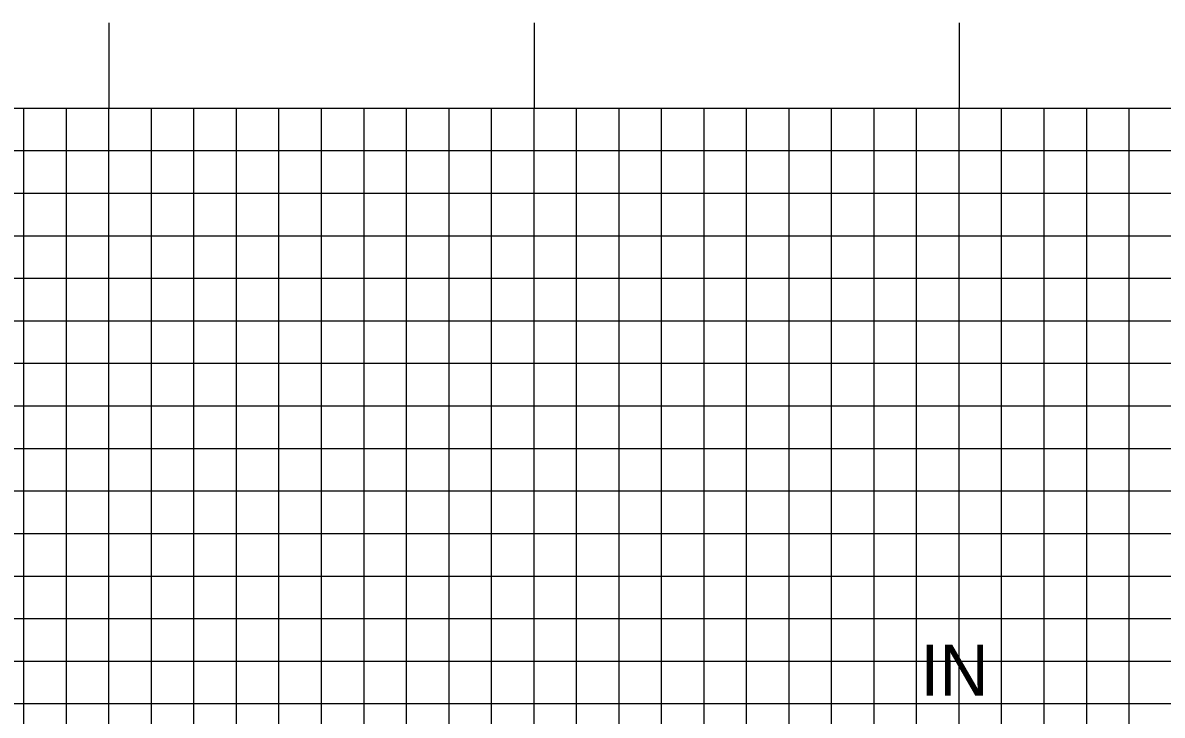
# Model space of a CAD drawing. Extents: x 851348 to 851692, y 364785 to 365005.
# Drawn here: x 851532.16 to 851558.97, y 364823.96 to 364840.24 of the extents above; entities that cross this region are included whole.
import ezdxf

# ---------------------------------------------------------------- set-up
doc = ezdxf.new("R2010")
doc.units = 0
for name, color, linetype in [('ANNOTATION', 7, 'Continuous'), ('MAJOR', 7, 'Continuous'), ('MINOR', 7, 'Continuous')]:
    doc.layers.add(name, color=color, linetype=linetype)

msp = doc.modelspace()

# ---------------------------------------------------------------- linework, layer by layer
at = {"layer": 'MAJOR'}
for p, q in [((851534.191, 364840.237), (851534.191, 364838.233)), ((851544.191, 364840.237), (851544.191, 364838.233)), ((851554.191, 364840.237), (851554.191, 364838.233)), ((851374.191, 364838.233), (851654.191, 364838.233)), ((851374.191, 364838.233), (851654.191, 364838.233)), ((851534.191, 364808.233), (851534.191, 364838.233)), ((851544.191, 364808.233), (851544.191, 364838.233)), ((851554.191, 364808.233), (851554.191, 364838.233)), ((851374.191, 364833.233), (851654.191, 364833.233)), ((851374.191, 364828.233), (851654.191, 364828.233))]:
    msp.add_line(p, q, dxfattribs=at)
at = {"layer": 'MINOR'}
for p, q in [((851532.191, 364808.233), (851532.191, 364838.233)), ((851533.191, 364808.233), (851533.191, 364838.233)), ((851535.191, 364808.233), (851535.191, 364838.233)), ((851536.191, 364808.233), (851536.191, 364838.233)), ((851537.191, 364808.233), (851537.191, 364838.233)), ((851538.191, 364808.233), (851538.191, 364838.233)), ((851539.191, 364808.233), (851539.191, 364838.233)), ((851540.191, 364808.233), (851540.191, 364838.233)), ((851541.191, 364808.233), (851541.191, 364838.233)), ((851542.191, 364808.233), (851542.191, 364838.233)), ((851543.191, 364808.233), (851543.191, 364838.233)), ((851545.191, 364808.233), (851545.191, 364838.233)), ((851546.191, 364808.233), (851546.191, 364838.233)), ((851547.191, 364808.233), (851547.191, 364838.233)), ((851548.191, 364808.233), (851548.191, 364838.233)), ((851549.191, 364808.233), (851549.191, 364838.233)), ((851550.191, 364808.233), (851550.191, 364838.233)), ((851551.191, 364808.233), (851551.191, 364838.233)), ((851552.191, 364808.233), (851552.191, 364838.233)), ((851553.191, 364808.233), (851553.191, 364838.233)), ((851555.191, 364808.233), (851555.191, 364838.233)), ((851556.191, 364808.233), (851556.191, 364838.233)), ((851557.191, 364808.233), (851557.191, 364838.233)), ((851558.191, 364808.233), (851558.191, 364838.233)), ((851374.191, 364837.233), (851654.191, 364837.233)), ((851374.191, 364836.233), (851654.191, 364836.233)), ((851374.191, 364835.233), (851654.191, 364835.233)), ((851374.191, 364834.233), (851654.191, 364834.233)), ((851374.191, 364832.233), (851654.191, 364832.233)), ((851374.191, 364831.233), (851654.191, 364831.233)), ((851374.191, 364830.233), (851654.191, 364830.233)), ((851374.191, 364829.233), (851654.191, 364829.233)), ((851374.191, 364827.233), (851654.191, 364827.233)), ((851374.191, 364826.233), (851654.191, 364826.233)), ((851374.191, 364825.233), (851654.191, 364825.233)), ((851374.191, 364824.233), (851654.191, 364824.233))]:
    msp.add_line(p, q, dxfattribs=at)

# ---------------------------------------------------------------- texts
at = {"layer": 'ANNOTATION'}
msp.add_text('IN', height=1.2, dxfattribs=at).set_placement((851553.278, 364824.418))

doc.saveas('drawing.dxf')
